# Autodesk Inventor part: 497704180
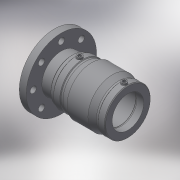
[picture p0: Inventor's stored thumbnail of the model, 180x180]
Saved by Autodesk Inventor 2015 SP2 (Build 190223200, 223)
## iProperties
Created: 2017-06
Part Number: 497704180
Material: Generic
Description: PLASSON PE CAST IRON SPIGOT COUPLER TRANSITION 225-200
Document SubType Name: Modeling
Designer: KIM
Mass: 55.0731 g
Surface Area: 148.067 cm^2
Volume: 55.0731 cm^3
Density: 1 g/cm^3
Appearance: Default
Author: KIM
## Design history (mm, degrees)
derived "497704.ipt"
feature "Solid1::497704.ipt"
tag "TaggingFeature1"
body "Solid1"
other parameters: "d13" = 212, "d14" = 17.6296, "d15" = 105, "d16" = 105, "d17" = 171, "d19" = 3.52592, "d20" = 168 deg, "d22" = 202.1, "d23" = 215, "d24" = 196.037, "d25" = 135 deg, "d26" = 84.8, "d27" = 135 deg, "d29" = 116, "d35" = 15, "d39" = 5 deg, "d45" = 4, "d46" = 14, "d47" = 0, "d50" = 3, "d51" = 0, "d52" = 30.45, "d53" = 7.6125, "d55" = 0.1, "d56" = 191.35, "d58" = 72, "d62" = 6.45, "d65" = 4.3, "d68" = 215, "d69" = 285, "d70" = 24, "d71" = 8, "d72" = 172.215, "d73" = 14.4, "d74" = 22, "d77" = 0, "d79" = 360 deg, "L_" = 284, "L_1" = 105, "D_1" = 215, "A_" = 116, "d_2" = 12, "L_2" = 72, "H_" = 109, "D_" = 285, "t_" = 24, "S_" = 22
